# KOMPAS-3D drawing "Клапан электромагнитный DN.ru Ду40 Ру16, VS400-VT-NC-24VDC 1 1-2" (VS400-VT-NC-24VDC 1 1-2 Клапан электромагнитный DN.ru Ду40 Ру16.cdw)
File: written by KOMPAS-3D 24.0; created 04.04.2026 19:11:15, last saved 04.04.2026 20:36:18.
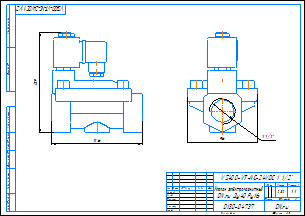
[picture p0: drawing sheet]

Document properties: c3d_UniqueCompID: ef56311e-7521-43dc-8291-0e6108b3d81d; Обозначение: VS400-ET-NC-220VAC 1; Наименование: Клапан электромагнитный DN.ru Ду25 Ру16; Автор: artio; Класс точности: c; Знак неуказанной шероховатости: Шероховатость не задана; Рассекать на разрезах: Да; c3d_UniqueCompID: ef56311e-7521-43dc-8291-0e6108b3d81d; Обозначение: VS400-ET-NC-220VAC 1-2; Наименование: Клапан электромагнитный DN.ru Ду15 Ру16; Автор: artio; Класс точности: c; Знак неуказанной шероховатости: Шероховатость не задана; Рассекать на разрезах: Да; c3d_UniqueCompID: ef56311e-7521-43dc-8291-0e6108b3d81d; Обозначение: VS400-ET-NC-220VAC 3-4; Наименование: Клапан электромагнитный DN.ru Ду20 Ру16; Автор: artio; Класс точности: c; Знак неуказанной шероховатости: Шероховатость не задана; Рассекать на разрезах: Да; c3d_UniqueCompID: ef56311e-7521-43dc-8291-0e6108b3d81d; Обозначение: VS400-ET-NC-220VAC 1 1-4; Наименование: Клапан электромагнитный DN.ru Ду32 Ру16; Автор: artio; Класс точности: c; Знак неуказанной шероховатости: Шероховатость не задана; Рассекать на разрезах: Да; c3d_UniqueCompID: ef56311e-7521-43dc-8291-0e6108b3d81d; Обозначение: VS400-ET-NC-220VAC 3-8; Наименование: Клапан электромагнитный DN.ru Ду10 Ру16; Автор: artio; Класс точности: c; Знак неуказанной шероховатости: Шероховатость не задана; Рассекать на разрезах: Да; c3d_UniqueCompID: ef56311e-7521-43dc-8291-0e6108b3d81d; Обозначение: VS400-ET-NC-220VAC 1 1-2; Наименование: Клапан электромагнитный DN.ru Ду40 Ру16; Автор: artio; Класс точности: c; Знак неуказанной шероховатости: Шероховатость не задана; Рассекать на разрезах: Да; Автор: artio; Форматы листов документа: A3; Полное имя файла: VS400-VT-NC-24VDC 1 1-2 Клапан электромагнитный DN.ru Ду40 Ру16.m3d; Масса: 2.321; Наименование: Клапан электромагнитный DN.ru Ду40 Ру16; Количество листов документа: 1; Примечание: D130-04737

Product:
- Body: Тело 1  | qty 1
    Масса: 4.144257
- Part/product: Клапан электромагнитный DN.ru Ду40 Ру16  | designation VS400-VT-NC-24VDC 1 1-2
    Масса: 2.321
    Раздел спецификации: Прочие изделия
    Примечание: D130-04737
    additional columns: ef56311e-7521-43dc-8291-0e6108b3d81d; VS400-ET-NC-220VAC 1 1-2; artio; c; Шероховатость не задана; Да

Views: Вид 1, Спереди
Referenced files in C:\Users\artio\OneDrive\Рабочий стол\Клапан электромагнитный DN.ru\VS400-ET-NC\VS400-ET-NC-24VDC\: VS400-ET-NC-24VDC 3-8 Клапан электромагнитный DN.ru Ду10 Ру16.m3d
Referenced files in C:\Users\artio\OneDrive\Рабочий стол\Клапан электромагнитный DN.ru\VS400-VT-NC\VS400-VT-NC-24VDC\: VS400-VT-NC-24VDC 1 1-2 Клапан электромагнитный DN.ru Ду40 Ру16.m3d
Referenced files in C:\Users\artio\OneDrive\Рабочий стол\Клапан электромагнитный DN.ru\VS400-ET-NC\: VS400-ET-NC-24VDC 3-8 Клапан электромагнитный DN.ru Ду10 Ру16.cdw
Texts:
  VS400-VT-NC-24VDC 1 1-2
  Клапан электромагнитный
  DN.ru Ду40 Ру16
  VS400-VT-NC-24VDC 1 1/2"
  VS400-VT-NC-24VDC 1 1/2"-
  Клапан электромагнитный DN.ru Ду40 Ру16
  VS400-VT-NC-24VDC 1 1-2 Клапан электромагнитный DN.ru Ду40 Ру16
Dimensions and other numbers on the sheet: 0; 3; 2; 4; 96; 1 1/2"; 1:1; 1; 2,32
